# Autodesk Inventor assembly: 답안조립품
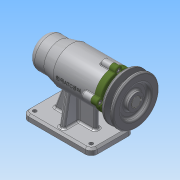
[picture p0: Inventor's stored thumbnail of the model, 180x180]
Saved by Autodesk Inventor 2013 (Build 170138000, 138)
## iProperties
Created: 2019-07
Part Number: 답안조립품
Document SubType Name: Assembly
Designer: Administrator
Author: Administrator
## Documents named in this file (12)
- C:\Users\Administrator\Desktop\490704V1079\답안조립품.iam
- C:\Users\Administrator\Desktop\490704V1079\본체.ipt
- C:\Users\Administrator\Desktop\490704V1079\V벨트풀리.ipt
- C:\Users\Administrator\Desktop\490704V1079\멈춤나사 M3.ipt
- C:\Users\Administrator\Desktop\490704V1079\베어링 6004.ipt
- C:\Users\Administrator\Desktop\490704V1079\베어링 51202.ipt
- C:\Users\Administrator\Desktop\490704V1079\볼트 M4.ipt
- C:\Users\Administrator\Desktop\490704V1079\어댑터슬리브.ipt
- C:\Users\Administrator\Desktop\490704V1079\오일 실.ipt
- C:\Users\Administrator\Desktop\490704V1079\축.ipt
- C:\Users\Administrator\Desktop\490704V1079\커버.ipt
- C:\Users\Administrator\Desktop\490704V1079\키 5 x 5 x 16.ipt
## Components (1 placed, 1 different names)
1. V벨트풀리:1
